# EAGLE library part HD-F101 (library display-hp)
LED DISPLAY 1-character 7 segment, decimal point right
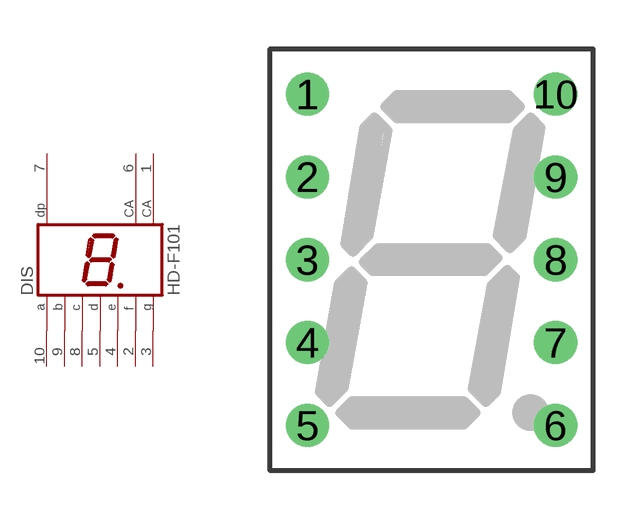
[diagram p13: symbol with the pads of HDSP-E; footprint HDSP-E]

Designator prefix DIS

## HD-F101 (OC_FARNELL: unknown; OC_NEWARK: unknown)  [HDSP-E]
1  CA  pas
2  F  pas
3  G  pas
4  E  pas
5  D  pas
6  CA  pas
7  DP  pas
8  C  pas
9  B  pas
10  A  pas

## Footprint HDSP-E (pad centres in mm)
LED DISPLAY 10-mm 1 character 7 segment, decimal point right
drill 0.813 round: 1 -3.81,5.08; 2 -3.81,2.54; 3 -3.81,0; 4 -3.81,-2.54; 5 -3.81,-5.08; 6 3.81,-5.08; 7 3.81,-2.54; 8 3.81,0; 9 3.81,2.54; 10 3.81,5.08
